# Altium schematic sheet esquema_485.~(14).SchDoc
size A4
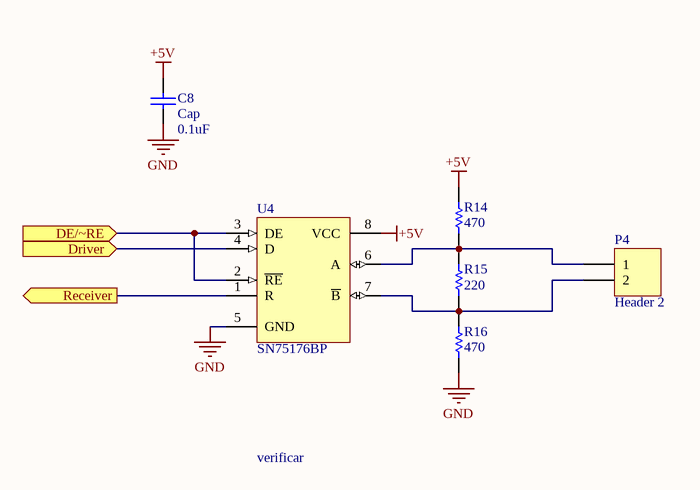
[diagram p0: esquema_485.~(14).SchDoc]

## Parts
C8  Cap  value 0.1uF  [RAD-0.3]
P4  Header 2  [HDR1X2]
R14  value 470  [1005[0402]]  (hidden comment: Carbon 1/8w 5%)
R15  value 220  [1005[0402]]  (hidden comment: Carbon 1/8w 5%)
R16  value 470  [1005[0402]]  (hidden comment: Carbon 1/8w 5%)
U4  SN75176BP  [P008]

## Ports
DE/~RE (in), Driver (in), Receiver (out)

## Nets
+5V: C8.2 R14.2 U4.8(VCC)
GND: C8.1 R16.1 U4.5(GND)
DE/~RE: U4.2(~{RE}) U4.3(DE) ; port DE/~RE
Driver: U4.4(D) ; port Driver
Receiver: U4.1(R) ; port Receiver
NetP4_1: P4.1 R14.1 R15.2 U4.6(A)
NetP4_2: P4.2 R15.1 R16.2 U4.7(~{B})

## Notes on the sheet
- verificar

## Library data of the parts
C8 = Cap: Capacitor
P4 = Header 2: Header, 2-Pin
R14-R16 = Res Semi: Semiconductor Resistor
U4 = SN75176BP: Differential Bus Transceiver; Note: Receiver Hysteresis of 50mV Typical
